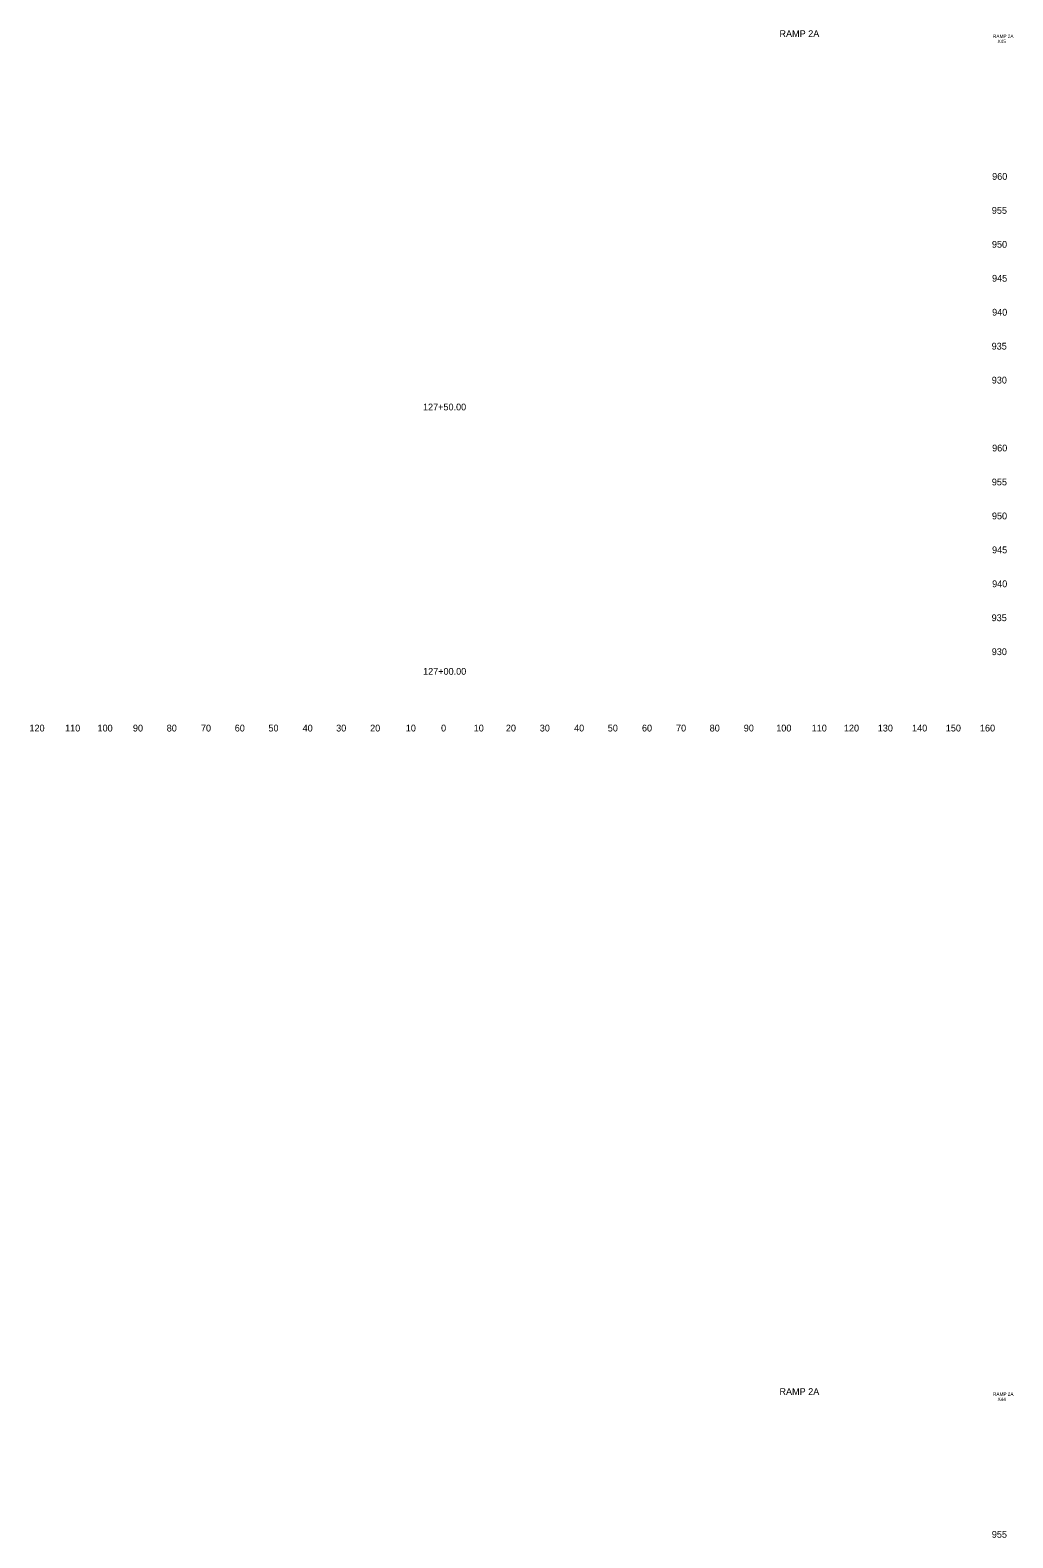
# Model space of a CAD drawing. Extents: x 4994 to 7388, y 4997 to 8804.
# Drawn here: x 7098.2 to 7387.8, y 6360 to 6804.1 of the extents above; entities that cross this region are included whole.
import ezdxf

# ---------------------------------------------------------------- set-up
doc = ezdxf.new("R2010")
doc.units = 0
for name, color, linetype in [('RD_SHT_ID', 7, 'Continuous'), ('RD_XS_TX_Offset', 7, 'Continuous'), ('RD_XS_TX_Station', 7, 'Continuous')]:
    doc.layers.add(name, color=color, linetype=linetype)

msp = doc.modelspace()

# ---------------------------------------------------------------- texts
at = {"layer": 'RD_SHT_ID'}
for s, height, p in [('RAMP 2A', 2, (7319.02, 6802.06)), ('RAMP 2A', 1, (7381.93, 6801.8)), ('X45', 1, (7383.29, 6800.3)), ('RAMP 2A', 2, (7319.02, 6402.06)), ('RAMP 2A', 1, (7381.93, 6401.8)), ('X44', 1, (7383.29, 6400.3))]:
    msp.add_text(s, height=height, dxfattribs=at).set_placement(p)
at = {"layer": 'RD_XS_TX_Offset'}
for s, p in [('960', (7381.69, 6760)), ('955', (7381.6, 6750)), ('950', (7381.63, 6740)), ('945', (7381.66, 6730)), ('940', (7381.69, 6720)), ('935', (7381.55, 6710)), ('930', (7381.58, 6700)), ('960', (7381.69, 6680)), ('955', (7381.6, 6670)), ('950', (7381.63, 6660)), ('945', (7381.66, 6650)), ('940', (7381.69, 6640)), ('935', (7381.55, 6630)), ('930', (7381.58, 6620)), ('120', (7098.01, 6597.5)), ('110', (7108.51, 6597.5)), ('100', (7118.07, 6597.5)), ('90', (7128.5, 6597.5)), ('80', (7138.46, 6597.5)), ('70', (7148.54, 6597.5)), ('60', (7158.5, 6597.5)), ('50', (7168.43, 6597.5)), ('40', (7178.5, 6597.5)), ('30', (7188.39, 6597.5)), ('20', (7198.4, 6597.5)), ('10', (7208.91, 6597.5)), ('0', (7219.3, 6597.5)), ('0', (7219.3, 6597.5)), ('10', (7228.91, 6597.5)), ('20', (7238.4, 6597.5)), ('30', (7248.39, 6597.5)), ('40', (7258.5, 6597.5)), ('50', (7268.43, 6597.5)), ('60', (7278.5, 6597.5)), ('70', (7288.54, 6597.5)), ('80', (7298.46, 6597.5)), ('90', (7308.5, 6597.5)), ('100', (7318.07, 6597.5)), ('110', (7328.51, 6597.5)), ('120', (7338.01, 6597.5)), ('130', (7347.99, 6597.5)), ('140', (7358.1, 6597.5)), ('150', (7368.04, 6597.5)), ('160', (7378.1, 6597.5)), ('955', (7381.6, 6360))]:
    msp.add_text(s, height=2, dxfattribs=at).set_placement(p)
at = {"layer": 'RD_XS_TX_Station'}
for s, p in [('127+50.00', (7213.98, 6692.09)), ('127+00.00', (7214.01, 6614.21))]:
    msp.add_text(s, height=2, dxfattribs=at).set_placement(p)

doc.saveas('drawing.dxf')
